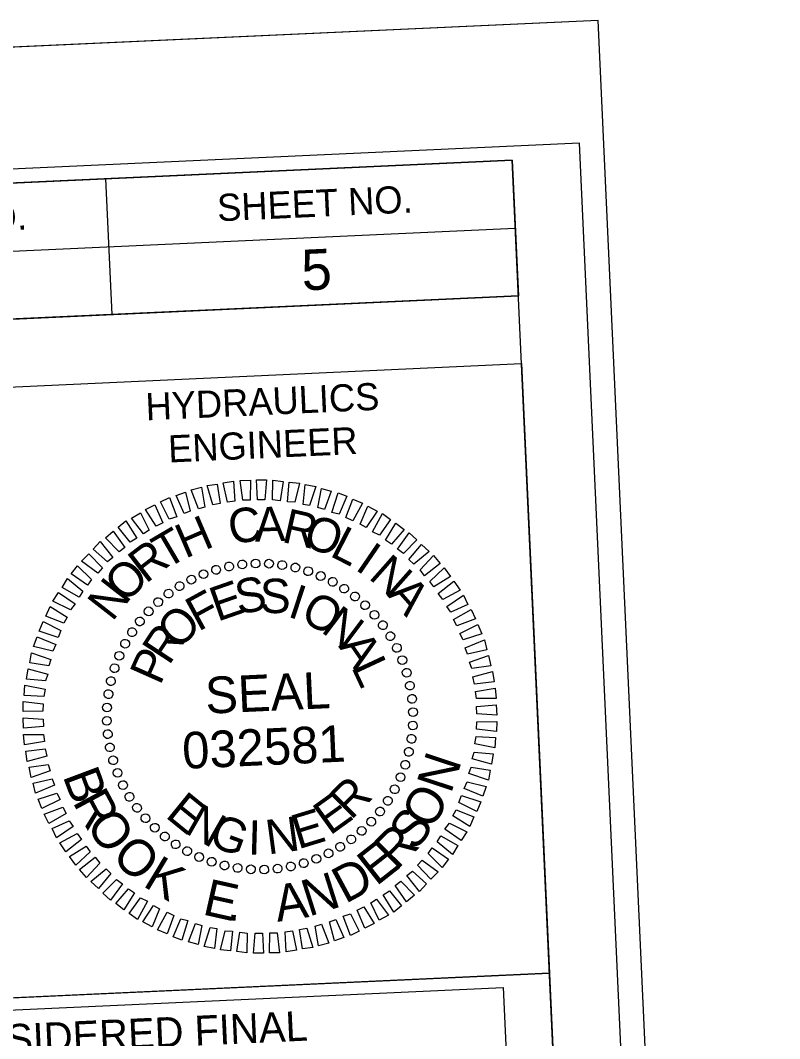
# Model space of a CAD drawing. Extents: x 1191070 to 1191932, y 892813 to 893283.
# Drawn here: x 1191747.2 to 1191803.2, y 893208.4 to 893283.5 of the extents above; entities that cross this region are included whole.
import ezdxf

# ---------------------------------------------------------------- set-up
doc = ezdxf.new("R2010")
doc.units = 0
for name, color, linetype in [('Sheet Border Standard 30in CELL', 7, 'Continuous'), ('Sheet Clip Boundary CELL', 7, 'Continuous'), ('Sheet Cutting Line CELL', 7, 'Continuous'), ('Sheet Data Field CELL', 7, 'Continuous'), ('Sheet PE Seal Cell', 7, 'Continuous'), ('Sheet Plot Border Inside CELL', 7, 'Continuous'), ('Sheet Plot Border Outside CELL', 7, 'Continuous'), ('Sheet Sticker Exception Certification CELL', 7, 'Continuous')]:
    doc.layers.add(name, color=color, linetype=linetype)

# ---------------------------------------------------------------- blocks, each defined once
blk = doc.blocks.new('STICKER EXCEPTION CERTIFICATION')
at = {"layer": 'Sheet Sticker Exception Certification CELL'}
for p, q in [((0, -0.47), (0, 0)), ((0, 0), (4.0008, 0)), ((4.0008, -0.0003), (4.0008, -0.4703)), ((4.0008, -0.47), (0, -0.47))]:
    blk.add_line(p, q, dxfattribs=at)
for s, p in [('DOCUMENT NOT CONSIDERED FINAL', (0.4214, -0.2069)), ('UNLESS ALL SIGNATURES COMPLETED', (0.32, -0.3829))]:
    blk.add_text(s, height=0.11, dxfattribs=at).set_placement(p)

msp = doc.modelspace()

# ---------------------------------------------------------------- linework, layer by layer
at = {"layer": 'Sheet Border Standard 30in CELL'}
for p, q in [((1191753.517, 893271.777), (1191753.974, 893261.787)), ((1191703.778, 893264.496), (1191783.714, 893268.153)), ((1191704.007, 893259.501), (1191783.943, 893263.158)), ((1191704.007, 893259.501), (1191783.943, 893263.158))]:
    msp.add_line(p, q, dxfattribs=at)
for points in [[(1191783.485, 893273.168), (1191184.112, 893245.747), (1191203.307, 892826.185), (1191802.68, 892853.607)], [(1191703.549, 893269.511), (1191783.485, 893273.168), (1191783.943, 893263.158), (1191704.007, 893259.501)], [(1191744.213, 893256.336), (1191784.171, 893258.164), (1191786.228, 893213.211), (1191746.27, 893211.383)]]:
    msp.add_lwpolyline(points, close=True, dxfattribs=at)
at = {"layer": 'Sheet Clip Boundary CELL'}
msp.add_lwpolyline([(1191201.309, 892936.071), (1191187.079, 893244.148), (1191703.387, 893267.995), (1191706.101, 893208.662), (1191782.814, 893212.171), (1191794.301, 892963.459), (1191451.083, 892947.607)], close=True, dxfattribs=at)
at = {"layer": 'Sheet Cutting Line CELL'}
msp.add_line((1191789.821, 893283.468), (1191116.925, 893252.683), dxfattribs=at)
at = {"layer": 'Sheet PE Seal Cell'}
for p, q in [((1191761.653, 893242.966), (1191761.653, 893242.966)), ((1191762.634, 893243.191), (1191762.634, 893243.191)), ((1191763.594, 893243.37), (1191763.594, 893243.37)), ((1191764.582, 893243.438), (1191764.582, 893243.438)), ((1191765.574, 893243.416), (1191765.574, 893243.416)), ((1191766.548, 893243.303), (1191766.548, 893243.303)), ((1191767.501, 893243.143), (1191767.501, 893243.143)), ((1191768.46, 893242.872), (1191768.46, 893242.872)), ((1191759.839, 893242.252), (1191759.839, 893242.252)), ((1191760.721, 893242.653), (1191760.721, 893242.653)), ((1191769.377, 893242.509), (1191769.377, 893242.509)), ((1191770.274, 893242.099), (1191770.274, 893242.099)), ((1191758.983, 893241.763), (1191758.983, 893241.763)), ((1191771.109, 893241.574), (1191771.109, 893241.574)), ((1191757.391, 893240.609), (1191757.391, 893240.609)), ((1191758.152, 893241.207), (1191758.152, 893241.207)), ((1191771.924, 893241.003), (1191771.924, 893241.003)), ((1191756.681, 893239.901), (1191756.681, 893239.901)), ((1191772.651, 893240.361), (1191772.651, 893240.361)), ((1191756.038, 893239.173), (1191756.038, 893239.173)), ((1191773.359, 893239.65), (1191773.359, 893239.65)), ((1191755.467, 893238.358), (1191755.467, 893238.358)), ((1191773.957, 893238.889), (1191773.957, 893238.889)), ((1191774.513, 893238.059), (1191774.513, 893238.059)), ((1191754.942, 893237.524), (1191754.942, 893237.524)), ((1191775.003, 893237.203), (1191775.003, 893237.203)), ((1191754.533, 893236.626), (1191754.533, 893236.626)), ((1191775.404, 893236.32), (1191775.404, 893236.32)), ((1191754.169, 893235.709), (1191754.169, 893235.709)), ((1191775.717, 893235.388), (1191775.717, 893235.388)), ((1191753.898, 893234.75), (1191753.898, 893234.75)), ((1191775.942, 893234.408), (1191775.942, 893234.408)), ((1191753.739, 893233.797), (1191753.739, 893233.797)), ((1191776.121, 893233.447), (1191776.121, 893233.447)), ((1191753.626, 893232.824), (1191753.626, 893232.824)), ((1191776.188, 893232.459), (1191776.188, 893232.459)), ((1191753.604, 893231.831), (1191753.604, 893231.831)), ((1191764.896, 893232.145), (1191764.896, 893232.145)), ((1191753.671, 893230.844), (1191753.671, 893230.844)), ((1191776.166, 893231.467), (1191776.166, 893231.467)), ((1191776.053, 893230.494), (1191776.053, 893230.494)), ((1191753.85, 893229.883), (1191753.85, 893229.883)), ((1191775.894, 893229.54), (1191775.894, 893229.54)), ((1191754.075, 893228.902), (1191754.075, 893228.902)), ((1191775.623, 893228.582), (1191775.623, 893228.582)), ((1191754.388, 893227.971), (1191754.388, 893227.971)), ((1191754.789, 893227.088), (1191754.789, 893227.088)), ((1191775.259, 893227.664), (1191775.259, 893227.664)), ((1191774.85, 893226.767), (1191774.85, 893226.767)), ((1191755.279, 893226.232), (1191755.279, 893226.232)), ((1191774.325, 893225.932), (1191774.325, 893225.932)), ((1191755.835, 893225.402), (1191755.835, 893225.402)), ((1191773.754, 893225.118), (1191773.754, 893225.118)), ((1191756.433, 893224.641), (1191756.433, 893224.641)), ((1191773.112, 893224.39), (1191773.112, 893224.39)), ((1191757.141, 893223.93), (1191757.141, 893223.93)), ((1191772.401, 893223.682), (1191772.401, 893223.682)), ((1191757.869, 893223.287), (1191757.869, 893223.287)), ((1191758.683, 893222.717), (1191758.683, 893222.717)), ((1191771.64, 893223.084), (1191771.64, 893223.084)), ((1191759.518, 893222.192), (1191759.518, 893222.192)), ((1191769.953, 893222.038), (1191769.953, 893222.038)), ((1191770.809, 893222.528), (1191770.809, 893222.528)), ((1191760.415, 893221.782), (1191760.415, 893221.782)), ((1191761.333, 893221.419), (1191761.333, 893221.419)), ((1191762.291, 893221.147), (1191762.291, 893221.147)), ((1191767.158, 893221.1), (1191767.158, 893221.1)), ((1191768.139, 893221.325), (1191768.139, 893221.325)), ((1191769.071, 893221.638), (1191769.071, 893221.638)), ((1191763.244, 893220.988), (1191763.244, 893220.988)), ((1191764.218, 893220.875), (1191764.218, 893220.875)), ((1191765.21, 893220.853), (1191765.21, 893220.853)), ((1191766.198, 893220.921), (1191766.198, 893220.921))]:
    msp.add_line(p, q, dxfattribs=at)
for points in [[(1191760.367, 893247.457), (1191759.83, 893248.851), (1191760.587, 893249.044), (1191760.833, 893247.591)], [(1191761.434, 893247.754), (1191761.009, 893249.176), (1191761.747, 893249.277), (1191761.97, 893247.846)], [(1191762.507, 893247.938), (1191762.194, 893249.365), (1191762.954, 893249.49), (1191763.043, 893248.03)], [(1191763.625, 893248.102), (1191763.446, 893249.557), (1191764.189, 893249.569), (1191764.166, 893248.104)], [(1191764.705, 893248.128), (1191764.639, 893249.589), (1191765.381, 893249.601), (1191765.246, 893248.131)], [(1191765.832, 893248.112), (1191765.855, 893249.577), (1191766.603, 893249.477), (1191766.376, 893248.047)], [(1191766.919, 893247.982), (1191767.056, 893249.43), (1191767.803, 893249.351), (1191767.462, 893247.939)], [(1191768.077, 893247.787), (1191768.235, 893249.258), (1191769.007, 893249.114), (1191768.554, 893247.696)], [(1191769.169, 893247.544), (1191769.443, 893248.953), (1191770.15, 893248.76), (1191769.648, 893247.409)], [(1191758.216, 893246.705), (1191757.572, 893247.982), (1191758.234, 893248.283), (1191758.772, 893246.866)], [(1191759.301, 893247.115), (1191758.722, 893248.44), (1191759.41, 893248.674), (1191759.766, 893247.294)], [(1191770.199, 893247.186), (1191770.651, 893248.626), (1191771.293, 893248.385), (1191770.723, 893247.052)], [(1191771.23, 893246.805), (1191771.731, 893248.157), (1191772.443, 893247.874), (1191771.736, 893246.581)], [(1191757.249, 893246.188), (1191756.472, 893247.414), (1191757.154, 893247.76), (1191757.734, 893246.413)], [(1191772.288, 893246.336), (1191772.836, 893247.644), (1191773.528, 893247.293), (1191772.727, 893246.085)], [(1191756.307, 893245.604), (1191755.42, 893246.78), (1191756.1, 893247.172), (1191756.722, 893245.894)], [(1191773.192, 893245.769), (1191773.919, 893247.108), (1191774.525, 893246.663), (1191773.699, 893245.522)], [(1191755.344, 893244.997), (1191754.46, 893246.106), (1191755.024, 893246.559), (1191755.826, 893245.29)], [(1191774.144, 893245.137), (1191774.92, 893246.411), (1191775.527, 893245.943), (1191774.586, 893244.842)], [(1191754.52, 893244.284), (1191753.505, 893245.319), (1191754.09, 893245.818), (1191754.934, 893244.596)], [(1191775.03, 893244.479), (1191775.899, 893245.69), (1191776.463, 893245.175), (1191775.473, 893244.161)], [(1191753.653, 893243.546), (1191752.619, 893244.49), (1191753.134, 893245.054), (1191754.066, 893243.88)], [(1191775.876, 893243.729), (1191776.794, 893244.83), (1191777.358, 893244.315), (1191776.229, 893243.385)], [(1191752.948, 893242.725), (1191751.759, 893243.594), (1191752.297, 893244.137), (1191753.291, 893243.101)], [(1191776.699, 893242.956), (1191777.687, 893244.015), (1191778.187, 893243.43), (1191777.035, 893242.521)], [(1191752.2, 893241.835), (1191750.991, 893242.658), (1191751.459, 893243.265), (1191752.496, 893242.254)], [(1191777.414, 893242.11), (1191778.472, 893243.105), (1191778.929, 893242.473), (1191777.703, 893241.696)], [(1191751.565, 893240.95), (1191750.316, 893241.659), (1191750.713, 893242.33), (1191751.837, 893241.391)], [(1191778.04, 893241.216), (1191779.192, 893242.124), (1191779.65, 893241.469), (1191778.375, 893240.78)], [(1191750.932, 893240.02), (1191749.642, 893240.637), (1191750.063, 893241.287), (1191751.273, 893240.441)], [(1191778.67, 893240.253), (1191779.893, 893241.098), (1191780.217, 893240.414), (1191778.959, 893239.839)], [(1191750.436, 893239.029), (1191749.129, 893239.533), (1191749.435, 893240.245), (1191750.686, 893239.469)], [(1191779.164, 893239.307), (1191780.459, 893240.042), (1191780.784, 893239.337), (1191779.411, 893238.823)], [(1191750.034, 893237.975), (1191748.617, 893238.428), (1191748.922, 893239.14), (1191750.236, 893238.48)], [(1191779.617, 893238.27), (1191780.961, 893238.917), (1191781.24, 893238.231), (1191779.863, 893237.808)], [(1191749.63, 893236.965), (1191748.218, 893237.306), (1191748.478, 893238.016), (1191749.855, 893237.449)], [(1191780.026, 893237.207), (1191781.44, 893237.79), (1191781.609, 893237.054), (1191780.204, 893236.742)], [(1191749.342, 893235.871), (1191747.935, 893236.099), (1191748.058, 893236.848), (1191749.5, 893236.351)], [(1191780.345, 893236.141), (1191781.741, 893236.632), (1191781.911, 893235.874), (1191780.501, 893235.675)], [(1191749.099, 893234.779), (1191747.697, 893234.895), (1191747.82, 893235.666), (1191749.257, 893235.259)], [(1191780.596, 893235.071), (1191782.043, 893235.453), (1191782.145, 893234.691), (1191780.711, 893234.536)], [(1191748.972, 893233.624), (1191747.527, 893233.693), (1191747.582, 893234.462), (1191749.06, 893234.169)], [(1191780.78, 893233.998), (1191782.233, 893234.245), (1191782.313, 893233.483), (1191780.85, 893233.461)], [(1191748.909, 893232.54), (1191747.446, 893232.518), (1191747.457, 893233.262), (1191748.929, 893233.082)], [(1191780.854, 893232.876), (1191782.312, 893233.01), (1191782.347, 893232.246), (1191780.879, 893232.336)], [(1191748.938, 893231.415), (1191747.48, 893231.281), (1191747.445, 893232.045), (1191748.913, 893231.955)], [(1191780.883, 893231.751), (1191782.346, 893231.773), (1191782.335, 893231.029), (1191780.863, 893231.209)], [(1191749.012, 893230.293), (1191747.559, 893230.046), (1191747.479, 893230.808), (1191748.942, 893230.83)], [(1191780.82, 893230.667), (1191782.265, 893230.598), (1191782.21, 893229.829), (1191780.733, 893230.122)], [(1191749.196, 893229.22), (1191747.749, 893228.838), (1191747.647, 893229.599), (1191749.081, 893229.755)], [(1191780.693, 893229.512), (1191782.095, 893229.396), (1191781.972, 893228.625), (1191780.535, 893229.032)], [(1191749.447, 893228.15), (1191748.051, 893227.658), (1191747.881, 893228.416), (1191749.291, 893228.616)], [(1191780.45, 893228.42), (1191781.857, 893228.191), (1191781.734, 893227.443), (1191780.292, 893227.94)], [(1191749.767, 893227.084), (1191748.352, 893226.501), (1191748.183, 893227.236), (1191749.588, 893227.548)], [(1191780.162, 893227.326), (1191781.574, 893226.985), (1191781.314, 893226.275), (1191779.937, 893226.842)], [(1191750.176, 893226.021), (1191748.831, 893225.374), (1191748.552, 893226.06), (1191749.929, 893226.483)], [(1191779.758, 893226.316), (1191781.175, 893225.863), (1191780.87, 893225.151), (1191779.556, 893225.811)], [(1191750.628, 893224.983), (1191749.333, 893224.248), (1191749.008, 893224.954), (1191750.381, 893225.468)], [(1191779.356, 893225.262), (1191780.663, 893224.758), (1191780.357, 893224.046), (1191779.106, 893224.822)], [(1191751.122, 893224.037), (1191749.899, 893223.193), (1191749.575, 893223.877), (1191750.833, 893224.452)], [(1191778.861, 893224.27), (1191780.15, 893223.654), (1191779.729, 893223.004), (1191778.519, 893223.849)], [(1191751.752, 893223.075), (1191750.6, 893222.167), (1191750.142, 893222.821), (1191751.417, 893223.51)], [(1191778.227, 893223.34), (1191779.476, 893222.632), (1191779.079, 893221.96), (1191777.955, 893222.9)], [(1191752.378, 893222.18), (1191751.32, 893221.186), (1191750.863, 893221.818), (1191752.089, 893222.595)], [(1191777.592, 893222.456), (1191778.801, 893221.632), (1191778.333, 893221.025), (1191777.296, 893222.037)], [(1191753.093, 893221.335), (1191752.105, 893220.276), (1191751.605, 893220.861), (1191752.758, 893221.77)], [(1191776.845, 893221.565), (1191778.033, 893220.696), (1191777.495, 893220.154), (1191776.501, 893221.189)], [(1191753.916, 893220.562), (1191752.998, 893219.461), (1191752.434, 893219.976), (1191753.563, 893220.906)], [(1191776.139, 893220.745), (1191777.173, 893219.801), (1191776.658, 893219.237), (1191775.726, 893220.411)], [(1191754.762, 893219.812), (1191753.894, 893218.601), (1191753.329, 893219.116), (1191754.319, 893220.129)], [(1191775.272, 893220.007), (1191776.287, 893218.972), (1191775.702, 893218.472), (1191774.858, 893219.695)], [(1191755.648, 893219.154), (1191754.873, 893217.88), (1191754.266, 893218.348), (1191755.206, 893219.449)], [(1191774.448, 893219.294), (1191775.332, 893218.185), (1191774.768, 893217.732), (1191773.966, 893219.001)], [(1191756.6, 893218.522), (1191755.873, 893217.182), (1191755.267, 893217.628), (1191756.093, 893218.769)], [(1191757.504, 893217.955), (1191756.956, 893216.646), (1191756.264, 893216.998), (1191757.065, 893218.205)], [(1191772.543, 893218.103), (1191773.32, 893216.877), (1191772.638, 893216.53), (1191772.058, 893217.878)], [(1191773.485, 893218.686), (1191774.372, 893217.511), (1191773.692, 893217.119), (1191773.07, 893218.397)], [(1191758.562, 893217.486), (1191758.061, 893216.134), (1191757.349, 893216.417), (1191758.056, 893217.71)], [(1191771.576, 893217.585), (1191772.22, 893216.309), (1191771.558, 893216.008), (1191771.02, 893217.425)], [(1191759.593, 893217.105), (1191759.141, 893215.665), (1191758.499, 893215.906), (1191759.069, 893217.239)], [(1191760.623, 893216.747), (1191760.349, 893215.338), (1191759.642, 893215.53), (1191760.144, 893216.882)], [(1191761.715, 893216.504), (1191761.557, 893215.032), (1191760.785, 893215.177), (1191761.238, 893216.594)], [(1191769.426, 893216.834), (1191769.962, 893215.439), (1191769.205, 893215.247), (1191768.959, 893216.7)], [(1191770.491, 893217.175), (1191771.07, 893215.851), (1191770.382, 893215.616), (1191770.026, 893216.997)], [(1191762.873, 893216.309), (1191762.736, 893214.861), (1191761.989, 893214.94), (1191762.33, 893216.352)], [(1191763.96, 893216.178), (1191763.937, 893214.713), (1191763.189, 893214.814), (1191763.416, 893216.244)], [(1191765.087, 893216.162), (1191765.154, 893214.701), (1191764.411, 893214.69), (1191764.546, 893216.16)], [(1191766.167, 893216.189), (1191766.346, 893214.733), (1191765.603, 893214.722), (1191765.626, 893216.187)], [(1191767.285, 893216.353), (1191767.598, 893214.926), (1191766.838, 893214.801), (1191766.749, 893216.261)], [(1191768.358, 893216.537), (1191768.783, 893215.115), (1191768.045, 893215.014), (1191767.822, 893216.445)]]:
    msp.add_lwpolyline(points, close=True, dxfattribs=at)
for centre, major_axis in [((1191763.595, 893243.356), (-0.037, 0.322)), ((1191764.577, 893243.427), (-0.009, 0.324)), ((1191765.562, 893243.412), (0.019, 0.323)), ((1191766.541, 893243.311), (0.047, 0.321)), ((1191760.738, 893242.637), (-0.119, 0.301)), ((1191761.668, 893242.96), (-0.093, 0.31)), ((1191762.623, 893243.2), (-0.065, 0.317)), ((1191767.508, 893243.125), (0.075, 0.315)), ((1191768.455, 893242.856), (0.102, 0.307)), ((1191769.375, 893242.505), (0.129, 0.297)), ((1191758.979, 893241.756), (-0.17, 0.276)), ((1191759.839, 893242.235), (-0.145, 0.29)), ((1191770.261, 893242.075), (0.154, 0.285)), ((1191758.164, 893241.204), (-0.193, 0.26)), ((1191771.106, 893241.57), (0.178, 0.271)), ((1191771.903, 893240.993), (0.201, 0.254)), ((1191757.4, 893240.583), (-0.215, 0.242)), ((1191772.648, 893240.348), (0.223, 0.235)), ((1191756.693, 893239.897), (-0.235, 0.223)), ((1191773.333, 893239.641), (0.242, 0.215)), ((1191756.049, 893239.153), (-0.254, 0.201)), ((1191773.954, 893238.877), (0.26, 0.193)), ((1191755.472, 893238.355), (-0.271, 0.178)), ((1191774.507, 893238.062), (0.276, 0.17)), ((1191754.966, 893237.51), (-0.285, 0.154)), ((1191754.537, 893236.624), (-0.297, 0.129)), ((1191774.986, 893237.202), (0.29, 0.145)), ((1191775.388, 893236.304), (0.301, 0.119)), ((1191754.186, 893235.704), (-0.307, 0.102)), ((1191775.711, 893235.373), (0.31, 0.093)), ((1191753.916, 893234.757), (-0.315, 0.075)), ((1191775.951, 893234.419), (0.317, 0.065)), ((1191753.731, 893233.79), (-0.321, 0.047)), ((1191753.63, 893232.811), (-0.323, 0.019)), ((1191776.107, 893233.446), (0.322, 0.037)), ((1191776.178, 893232.464), (0.324, 0.009)), ((1191753.615, 893231.826), (-0.324, -0.009)), ((1191776.162, 893231.48), (0.323, -0.019)), ((1191753.685, 893230.844), (-0.322, -0.037)), ((1191776.062, 893230.501), (0.321, -0.047)), ((1191753.841, 893229.872), (-0.317, -0.065)), ((1191775.876, 893229.534), (0.315, -0.075)), ((1191754.081, 893228.917), (-0.31, -0.093)), ((1191775.606, 893228.587), (0.307, -0.102)), ((1191754.404, 893227.987), (-0.301, -0.119)), ((1191775.255, 893227.667), (0.297, -0.129)), ((1191754.806, 893227.089), (-0.29, -0.145)), ((1191774.826, 893226.781), (0.285, -0.154)), ((1191755.285, 893226.228), (-0.276, -0.17)), ((1191755.838, 893225.413), (-0.26, -0.193)), ((1191774.32, 893225.936), (0.271, -0.178)), ((1191756.459, 893224.649), (-0.242, -0.215)), ((1191773.743, 893225.138), (0.254, -0.201)), ((1191757.144, 893223.943), (-0.223, -0.235)), ((1191773.099, 893224.394), (0.235, -0.223)), ((1191757.889, 893223.298), (-0.201, -0.254)), ((1191771.628, 893223.087), (0.193, -0.26)), ((1191772.392, 893223.708), (0.215, -0.242)), ((1191758.687, 893222.721), (-0.178, -0.271)), ((1191759.532, 893222.216), (-0.154, -0.285)), ((1191770.813, 893222.535), (0.17, -0.276)), ((1191760.417, 893221.786), (-0.129, -0.297)), ((1191769.054, 893221.653), (0.119, -0.301)), ((1191769.953, 893222.056), (0.145, -0.29)), ((1191761.337, 893221.435), (-0.102, -0.307)), ((1191762.284, 893221.166), (-0.075, -0.315)), ((1191763.251, 893220.98), (-0.047, -0.321)), ((1191764.231, 893220.879), (-0.019, -0.323)), ((1191765.215, 893220.864), (0.009, -0.324)), ((1191766.197, 893220.935), (0.037, -0.322)), ((1191767.169, 893221.091), (0.065, -0.317)), ((1191768.124, 893221.331), (0.093, -0.31))]:
    msp.add_ellipse(centre, major_axis=major_axis, ratio=0.999708, dxfattribs=at)
at = {"layer": 'Sheet Plot Border Inside CELL'}
msp.add_lwpolyline([(1191788.433, 893274.415), (1191122.53, 893243.95), (1191141.818, 892822.351), (1191807.721, 892852.816)], close=True, dxfattribs=at)
at = {"layer": 'Sheet Plot Border Outside CELL'}
msp.add_lwpolyline([(1191789.821, 893283.468), (1191116.925, 893252.683), (1191137.034, 892813.143), (1191809.93, 892843.928)], close=True, dxfattribs=at)

# ---------------------------------------------------------------- block references
at = {"layer": 'Sheet Sticker Exception Certification CELL', "xscale": 20, "yscale": 19.999999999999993, "rotation": 2.6194666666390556}
msp.add_blockref('STICKER EXCEPTION CERTIFICATION', (1191706.292, 893209.554), dxfattribs=at)

# ---------------------------------------------------------------- texts
at = {"layer": 'Sheet Border Standard 30in CELL'}
for s, height, p in [('SHEET NO.', 2, (1191761.789, 893268.652)), ('PROJECT REFERENCE NO.', 2.00004, (1191712.578, 893266.44)), ('HYDRAULICS', 2, (1191756.514, 893253.975)), ('ENGINEER', 2, (1191758.178, 893250.868))]:
    msp.add_text(s, height=height, rotation=2.61947, dxfattribs=at).set_placement(p)
at = {"layer": 'Sheet Data Field CELL'}
msp.add_text('5', height=3, rotation=2.61947, dxfattribs=at).set_placement((1191768.022, 893263.551))
at = {"layer": 'Sheet PE Seal Cell'}
for s, height, rotation, p in [('C', 2.537, 8.83934, (1191762.762, 893244.819)), ('A', 2.537, 1.63979, (1191764.532, 893245.035)), ('R', 2.537, 347.24056, (1191766.424, 893245.031)), ('H', 2.537, 23.23894, (1191759.387, 893243.763)), ('O', 2.537, 340.04063, (1191767.945, 893244.763)), ('T', 2.537, 30.43924, (1191757.96, 893242.955)), ('L', 2.537, 332.84034, (1191769.961, 893244.022)), ('R', 2.537, 37.63997, (1191756.477, 893241.896)), ('I', 2.537, 325.63961, (1191771.831, 893243.026)), ('N', 2.537, 318.43837, (1191772.829, 893242.374)), ('O', 2.537, 44.84121, (1191754.989, 893240.431)), ('N', 2.537, 52.04297, (1191754.015, 893239.08)), ('E', 2.537, 19.23053, (1191761.762, 893239.119)), ('S', 2.537, 9.87507, (1191763.291, 893239.662)), ('S', 2.537, 0.51987, (1191764.908, 893239.759)), ('F', 2.537, 28.5865, (1191760.354, 893238.379)), ('I', 2.537, 341.80907, (1191766.855, 893239.533)), ('A', 2.537, 311.23662, (1191774.216, 893241.108)), ('O', 2.537, 332.45295, (1191767.769, 893239.259)), ('O', 2.537, 47.30071, (1191758.931, 893236.985)), ('N', 2.537, 323.09608, (1191769.316, 893238.429)), ('R', 2.538, 56.65912, (1191758.195, 893235.848)), ('A', 2.538, 304.37973, (1191770.651, 893237.319)), ('P', 2.538, 66.01836, (1191757.541, 893234.377)), ('L', 2.538, 295.02032, (1191771.598, 893235.808)), ('SEAL', 2.6992, 2.61947, (1191760.923, 893232.346)), ('032581', 2.6992, 2.61947, (1191759.23, 893228.279)), ('N', 2.699, 71.62642, (1191778.967, 893226.398)), ('B', 2.699, 290.58332, (1191750.341, 893227.767)), ('R', 2.537, 45.10087, (1191771.599, 893224.456)), ('R', 2.699, 298.27995, (1191751.058, 893225.857)), ('E', 2.537, 320.89636, (1191757.846, 893224.773)), ('E', 2.537, 35.74356, (1191770.052, 893223.327)), ('O', 2.699, 60.06601, (1191777.53, 893223.695)), ('N', 2.537, 330.25342, (1191759.25, 893223.621)), ('O', 2.699, 305.76021, (1191751.995, 893224.109)), ('G', 2.537, 339.60971, (1191761.004, 893222.688)), ('E', 2.537, 17.03123, (1191767.71, 893222.341)), ('S', 2.699, 52.7403, (1191776.349, 893222.153)), ('I', 2.537, 358.32067, (1191763.988, 893221.968)), ('N', 2.537, 7.67586, (1191765.497, 893221.97)), ('R', 2.699, 45.26004, (1191774.951, 893220.747)), ('O', 2.699, 317.32062, (1191753.867, 893221.687)), ('E', 2.699, 38.1507, (1191773.463, 893219.59)), ('K', 2.699, 328.88102, (1191756.186, 893219.689)), ('D', 2.699, 28.27491, (1191771.183, 893218.307)), ('N', 2.699, 17.54908, (1191768.498, 893217.379)), ('E', 2.699, 347.3653, (1191760.585, 893217.57)), ('A', 2.699, 8.70877, (1191766.185, 893217.001)), ('.', 2.699, 354.47464, (1191762.422, 893217.149))]:
    msp.add_text(s, height=height, rotation=rotation, dxfattribs=at).set_placement(p)

doc.saveas('drawing.dxf')
